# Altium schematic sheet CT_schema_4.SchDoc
size 288 x 169 mm
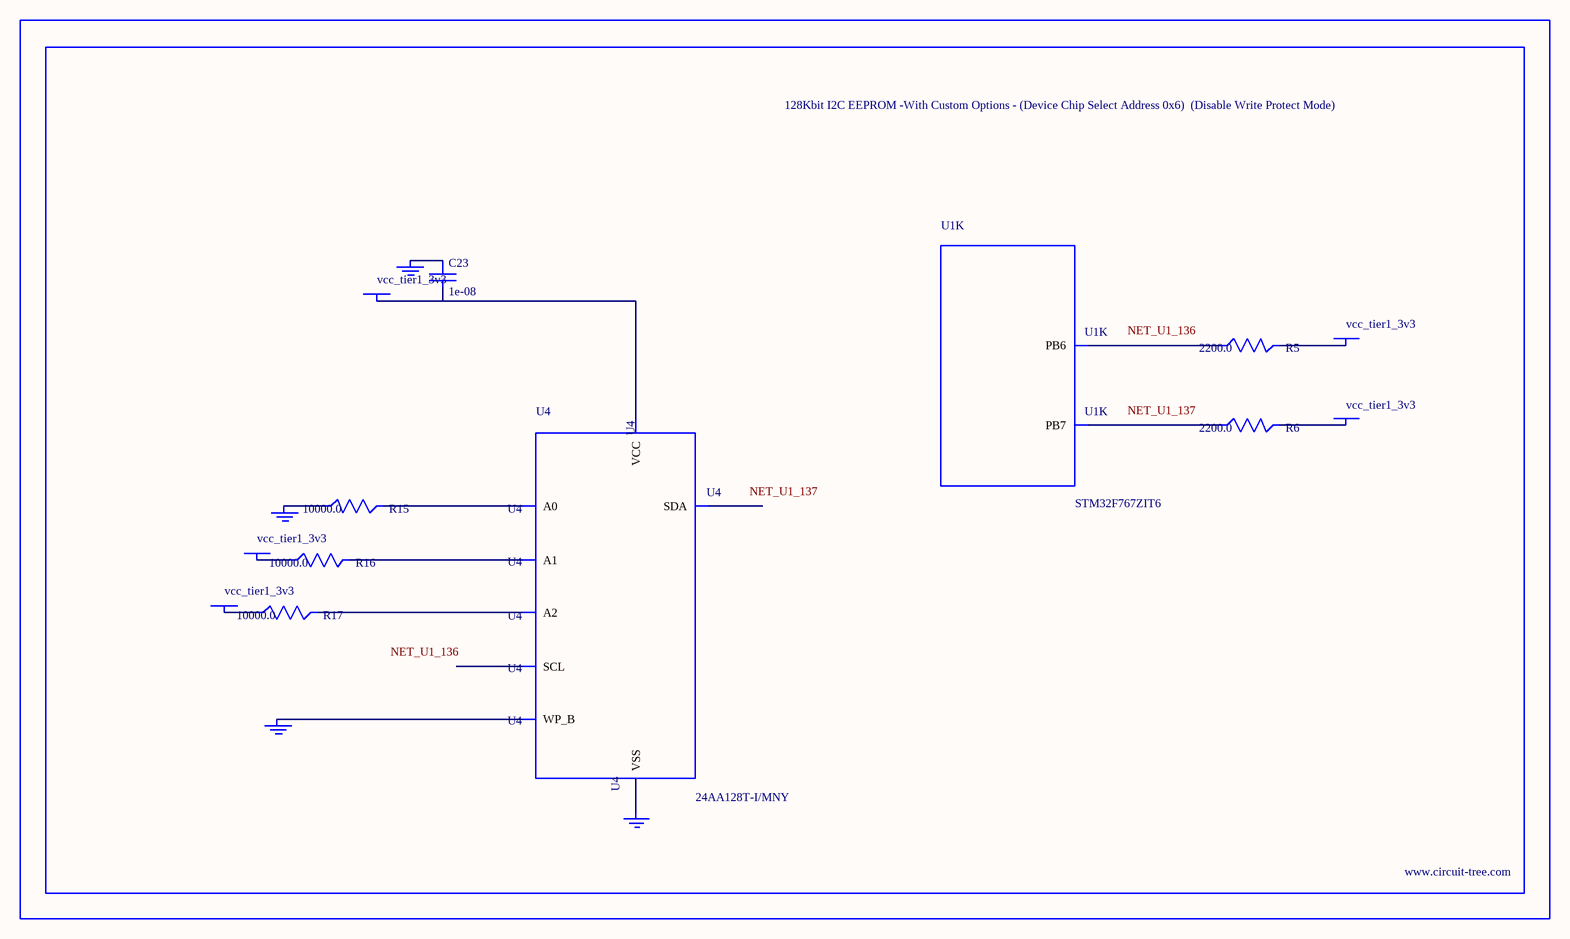
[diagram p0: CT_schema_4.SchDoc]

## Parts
BORDER3  (no value)
C23  1e-08  [C0402]
GND_INSTANCE_3_0  (no value)
GND_INSTANCE_3_1  (no value)
GND_INSTANCE_3_2  (no value)
GND_INSTANCE_3_3  (no value)
POWER_INSTANCE_3_0  vcc_tier1_3v3
POWER_INSTANCE_3_1  vcc_tier1_3v3
POWER_INSTANCE_3_2  vcc_tier1_3v3
POWER_INSTANCE_3_3  vcc_tier1_3v3
POWER_INSTANCE_3_4  vcc_tier1_3v3
R5  2200.0  [R0603]
R6  2200.0  [R0603]
R15  10000.0  [R0603]
R16  10000.0  [R0603]
R17  10000.0  [R0603]
U1  STM32F767ZIT6  [LQFP144]  (part K of 13)
U4  24AA128T-I/MNY  [TDFN-8/6MM]

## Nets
NetC23_1: C23.1 GND_INSTANCE_3_2.0(GND)
NetC23_2: C23.2 POWER_INSTANCE_3_2.0(PWR) U4.8(VCC)
NetGND_INSTANCE_3_0_0: GND_INSTANCE_3_0.0(GND) R15.1
NetGND_INSTANCE_3_1_0: GND_INSTANCE_3_1.0(GND) U4.7(WP_B)
NetGND_INSTANCE_3_3_0: GND_INSTANCE_3_3.0(GND) U4.4(VSS)
NetPOWER_INSTANCE_3_0_0: POWER_INSTANCE_3_0.0(PWR) R16.1
NetPOWER_INSTANCE_3_1_0: POWER_INSTANCE_3_1.0(PWR) R17.1
NetPOWER_INSTANCE_3_3_0: POWER_INSTANCE_3_3.0(PWR) R5.2
NetPOWER_INSTANCE_3_4_0: POWER_INSTANCE_3_4.0(PWR) R6.2
NetR5_1: R5.1 U1.136(PB6)
NetR6_1: R6.1 U1.137(PB7)
NetR15_2: R15.2 U4.1(A0)
NetR16_2: R16.2 U4.2(A1)
NetR17_2: R17.2 U4.3(A2)

Not connected (* = marked no-connect by the designer): U4 5(SDA) 6(SCL)

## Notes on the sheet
- Labels drawn without touching a wire or pin: NET_U1_136, NET_U1_137

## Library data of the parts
BORDER3 = BORDER_PAGE3
C23 = C0402C103K3RAC
GND_INSTANCE_3_0-GND_INSTANCE_3_3 = GND
POWER_INSTANCE_3_0-POWER_INSTANCE_3_4 = PWR
R5 R6 = RC0603JR-072K2L
R15-R17 = RC0603JR-0710KL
